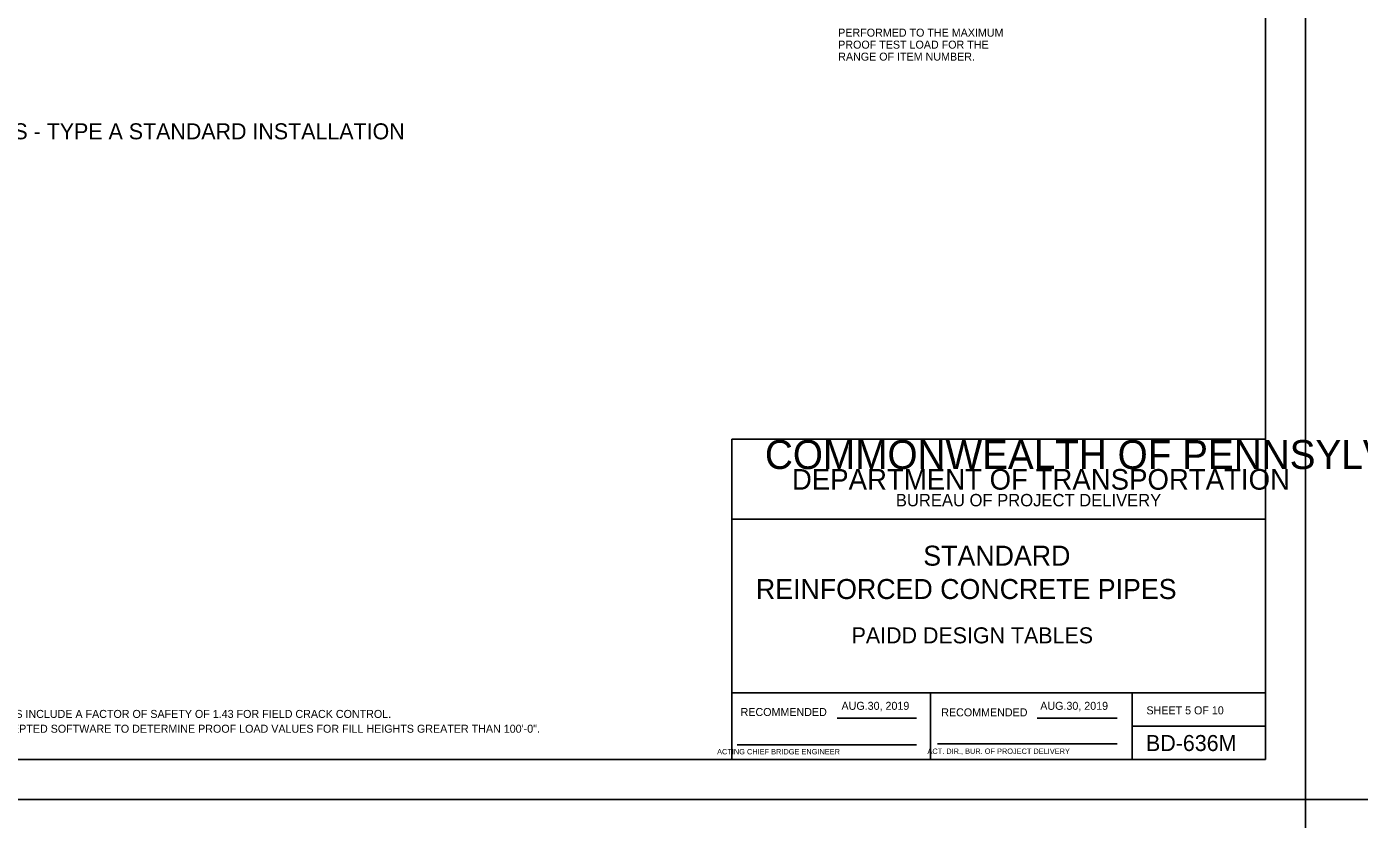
# Model space of a CAD drawing. Extents: x -22562 to -18409, y 3991 to 7171.
# Drawn here: x -20023.2 to -19523.6, y 5171.9 to 5469.1 of the extents above; entities that cross this region are included whole.
import ezdxf

# ---------------------------------------------------------------- set-up
doc = ezdxf.new("R2010")
doc.units = 0
for name, color, linetype in [('1', 7, 'Continuous'), ('2', 7, 'Continuous'), ('PLT-BNDY', 7, 'Continuous')]:
    doc.layers.add(name, color=color, linetype=linetype)

msp = doc.modelspace()

# ---------------------------------------------------------------- linework, layer by layer
at = {"layer": '2'}
for p, q in [((-19558.85, 5758.37), (-19558.85, 5194.37)), ((-19558.85, 5314.37), (-19758.85, 5314.37)), ((-19758.85, 5314.37), (-19758.85, 5194.37)), ((-19558.85, 5194.37), (-19558.85, 5314.37)), ((-19558.85, 5284.37), (-19758.85, 5284.37)), ((-19558.85, 5219.37), (-19758.85, 5219.37)), ((-19684.35, 5194.37), (-19684.35, 5219.37)), ((-19608.85, 5219.37), (-19608.85, 5194.37)), ((-19719.38, 5209.87), (-19689.62, 5209.87)), ((-19644.38, 5209.87), (-19614.47, 5209.87)), ((-19608.85, 5206.87), (-19558.85, 5206.87)), ((-19756.85, 5199.87), (-19689.62, 5199.87)), ((-19681.72, 5200.24), (-19614.47, 5200.24)), ((-19558.85, 5194.37), (-20344.85, 5194.37)), ((-19758.85, 5194.37), (-19558.85, 5194.37))]:
    msp.add_line(p, q, dxfattribs=at)
at = {"layer": 'PLT-BNDY'}
for points in [[(-20384.85, 5773.37), (-19543.85, 5773.37), (-19543.85, 5179.37), (-20384.85, 5179.37)], [(-19543.85, 5773.37), (-18702.85, 5773.37), (-18702.85, 5179.37), (-19543.85, 5179.37)], [(-20384.85, 5179.37), (-19543.85, 5179.37), (-19543.85, 4585.37), (-20384.85, 4585.37)]]:
    msp.add_lwpolyline(points, close=True, dxfattribs=at)

# ---------------------------------------------------------------- texts
at = {"layer": '1'}
for s, p in [('THESE PROOF LOADS INCLUDE A FACTOR OF SAFETY OF 1.43 FOR FIELD CRACK CONTROL.', (-20068.25, 5209.9)), ('USE PENNDOT ACCEPTED SOFTWARE TO DETERMINE PROOF LOAD VALUES FOR FILL HEIGHTS GREATER THAN 100\'-0".', (-20067.27, 5204.35))]:
    msp.add_text(s, height=3, dxfattribs=at).set_placement(p)
at = {"layer": '2'}
for s, height, p in [('  PERFORMED TO THE MAXIMUM', 3, (-19721.22, 5465.37)), ('  PROOF TEST LOAD FOR THE', 3, (-19721.22, 5460.87)), ('  RANGE OF ITEM NUMBER.', 3, (-19721.22, 5456.37)), ('PROOF TEST LOAD TABLE FOR CIRCULAR PIPES - TYPE A STANDARD INSTALLATION', 6, (-20214.1, 5426.87)), ('COMMONWEALTH OF PENNSYLVANIA', 10.8525, (-19746.47, 5303.24)), ('DEPARTMENT OF TRANSPORTATION', 7.7332, (-19736.35, 5295.49)), ('BUREAU OF PROJECT DELIVERY', 4.6493, (-19697.39, 5289.24)), ('STANDARD', 7.5, (-19687.1, 5266.99)), ('REINFORCED CONCRETE PIPES', 7.5, (-19749.85, 5254.49)), ('PAIDD DESIGN TABLES', 6, (-19713.97, 5237.87)), ('AUG.30, 2019', 3, (-19717.76, 5212.94)), ('AUG.30, 2019', 3, (-19643.25, 5212.94)), ('SHEET 5 OF 10', 3, (-19603.44, 5211.24)), ('BD-636M', 6, (-19603.6, 5197.49)), ('       ACTING CHIEF BRIDGE ENGINEER', 2.0002, (-19769.76, 5196.24)), ('   ACT. DIR., BUR. OF PROJECT DELIVERY', 2.0002, (-19687.84, 5196.42))]:
    msp.add_text(s, height=height, dxfattribs=at).set_placement(p)
for p in [(-19755.58, 5210.62), (-19680.36, 5210.49)]:
    msp.add_text('RECOMMENDED', height=3, rotation=360, dxfattribs=at).set_placement(p)

doc.saveas('drawing.dxf')
